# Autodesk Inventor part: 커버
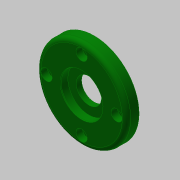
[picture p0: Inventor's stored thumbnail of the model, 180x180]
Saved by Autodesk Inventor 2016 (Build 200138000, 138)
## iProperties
Created: 2019-06
Part Number: 커버
Material: 알루미늄 6061
Document SubType Name: Modeling
Designer: mduedu
Density: 1 g/cm^3
Appearance: 진녹색
Author: mduedu
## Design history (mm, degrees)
sketch "스케치1"
  geometry: L1 (0, 0)-(9, 0); L2 (9, 0)-(9, 32); L3 (9, 32)-(0, 32); L4 (0, 32)-(0, 0); L5 (9, 0)-(12, 0); L6 (12, 0)-(12, 20); L7 (12, 20)-(9, 20); L8 (9, 20)-(9, 0)
  constraints: 16 end point, 4 parallel, 2 horizontal, 2 perpendicular
  dimensions: "d0" = 64 diameter of L3 L1; "d2" = 40 diameter of L7 L5; "d3" = 12 distance between parallel lines of L6 L4; "d4" = 3 distance between parallel lines of L2 L6
revolve "회전1" sketch "스케치1" stored, may be unused: angle "d5" = 90 deg
sketch "스케치2"
  geometry: L1 (0, 0)-(5.2, 0); L2 (5.2, 0)-(5.2, 15); L3 (5.2, 15)-(0, 15); L4 (0, 15)-(0, 0); L5 (5.2, 0)-(9, 0); L6 (9, 0)-(9, 9); L7 (9, 9)-(5.2, 9); L8 (5.2, 9)-(5.2, 0); L9 (9, 0)-(12, 0); L10 (12, 0)-(12, 15); L11 (12, 15)-(9, 15); L12 (9, 15)-(9, 0); L13 (12, -20)-(12, 20) reference
  constraints: 24 end point, 6 parallel, 3 horizontal, 3 perpendicular, 1 collinear
  dimensions: "d6" = 30 diameter of L3 L1; "d8" = 30 diameter of L11 L9; "d9" = 18 diameter of L7 L5; "d10" = 5.2 distance of L2.end L3.end; "d11" = 3 distance between parallel lines of L10 L12
revolve "회전2" sketch "스케치2" stored, may be unused: angle "d12" = 90 deg
fillet "모깎기1" dims "d13" = 3
fillet "모깎기2" dims "d14" = 3
chamfer "모따기1" distance "d15" = 1; stored, may be unused: second distance "d16" = 2, angle "d17" = 45 deg
sketch "스케치3" dims "d18" = 50
  geometry: 3 further points
  constraints: 2 vertical alignment, 1 coincident, 2 other
hole "구멍1" sketch "스케치3" at (0, 25) diameter "d19" = 4.5; stored, may be unused: countersink angle "d23" = 90 deg, drill point angle "d25" = 118 deg; dims "d20" = 6, "d21" = 8, "d22" = 4.6, "d24" = 8
chamfer "모따기2" distance "d29" = 0.5; stored, may be unused: second distance "d30" = 2, angle "d31" = 30 deg
node "솔리드1"
pattern_circular "원형 패턴1" dims angle "d27" = 360 deg
